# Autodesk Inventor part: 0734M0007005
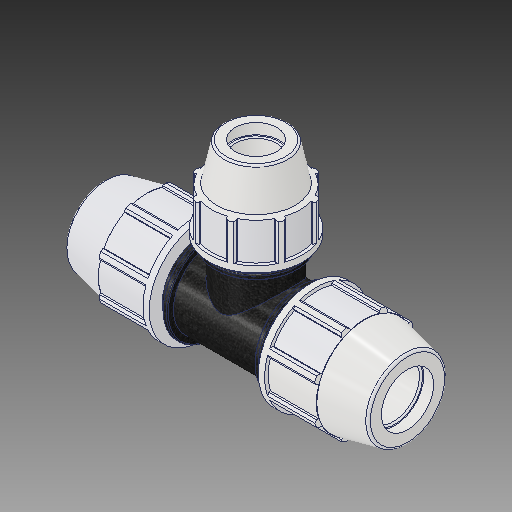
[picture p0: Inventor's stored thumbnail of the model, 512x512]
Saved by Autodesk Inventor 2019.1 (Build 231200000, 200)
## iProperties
Created: 2017-02
Part Number: 0734M0007005
Material: PVC-Piping
Description: PLASSON REDUCING TEE 3/4'' - 1/2'' - 3/4''
Document SubType Name: Modeling
Designer: KIM
Mass: 92.6774 g
Surface Area: 199.44 cm^2
Volume: 66.1981 cm^3
Density: 1.4 g/cm^3
Appearance: PTFE
Author: Кирилл
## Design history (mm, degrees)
derived "0734M0.ipt"
feature "Solid1::0734M0.ipt"
feature "Solid2::0734M0.ipt"
tag "TaggingFeature1"
body "Solid1"
other parameters: "d2" = 26.6, "d4" = 6.4135, "d5" = 21.54936, "d7" = 53.086, "d11" = 2.5654, "d13" = 120 deg, "d14" = 39.9, "d15" = 12 deg, "d16" = 46.18482, "d18" = 1.33, "d19" = 35 deg, "d20" = 17.5 deg, "d21" = 49.36998, "d23" = 0, "d25" = 360 deg, "d27" = 1.06172, "d33" = 0.532, "d42" = 27.70632, "d43" = 1.59258, "d46" = 0.798, "d67" = 39.8145, "d76" = 21.2, "d77" = 48.006, "d78" = 12 deg, "d79" = 75.946, "d80" = 120 deg, "d81" = 31.8, "d82" = 6.32883, "d87" = 2.53153, "d89" = 18.9865, "d90" = 22.7838, "d96" = 12.827, "d98" = 44.64558, "d99" = 35 deg, "d100" = 17.5 deg, "d102" = 0, "d103" = 0.96012, "d107" = 360 deg, "d109" = 0.636, "d112" = 1.06, "d113" = 3.2004, "d114" = 0, "d117" = 153.924, "d118" = 41.76522, "d126" = 23.94, "d127" = 59.944, "d131" = 3.03784, "d132" = 19.08, "d133" = 57.912, "d135" = 0, "d138" = 3.07848, "d143" = 0, "d148" = 36.0045, "d168" = 23.94, "d170" = 0, "d171" = 21.2, "d173" = 0, "d176" = 3.2004, "d177" = 0, "d_" = 26.6, "E_" = 53.086, "A_" = 75.946, "l_" = 59.944, "E_1" = 48.006, "l_1" = 57.912, "d_1" = 21.2, "H_" = 153.924
